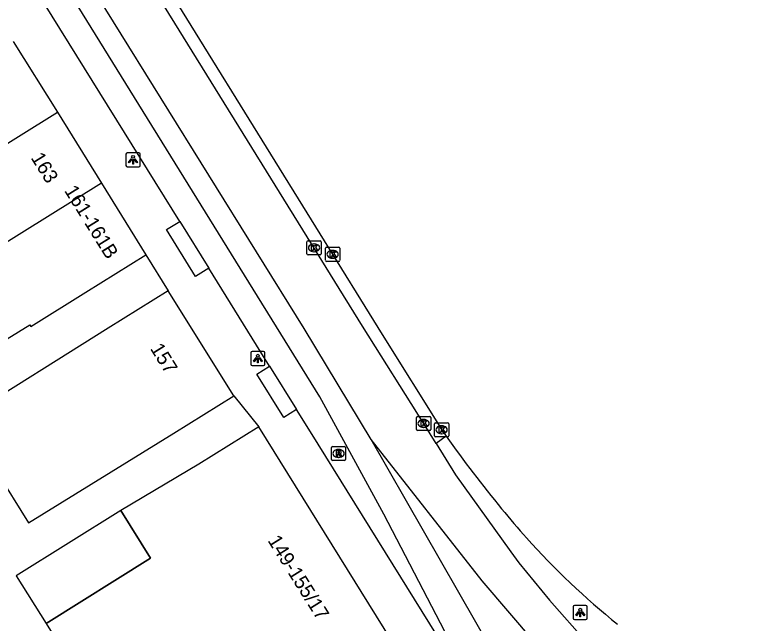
# Model space of a CAD drawing. Extents: x 159888 to 160757, y 384031 to 384746.
# Drawn here: x 160691.6 to 160744.8, y 384165.5 to 384208.5 of the extents above; entities that cross this region are included whole.
import ezdxf

# ---------------------------------------------------------------- set-up
doc = ezdxf.new("R2010")
doc.units = 0
for name, color, linetype in [('IMGEO_Berm_open', 7, 'Continuous'), ('IMGEO_Kolk', 7, 'Continuous'), ('IMGEO_Lichtpunt', 7, 'Continuous'), ('IMGEO_Pand', 7, 'Continuous'), ('IMGEO_Pand_nummerreeks', 7, 'Continuous'), ('IMGEO_Pand_overbouw', 7, 'Continuous'), ('IMGEO_Rijbaan_lokaal_gesloten', 7, 'Continuous'), ('IMGEO_Rioolput', 7, 'Continuous'), ('IMGEO_Voetpad_open', 7, 'Continuous')]:
    doc.layers.add(name, color=color, linetype=linetype)

msp = doc.modelspace()

# ---------------------------------------------------------------- linework, layer by layer
at = {"layer": 'IMGEO_Berm_open'}
msp.add_lwpolyline([(160722.103, 384178.75), (160721.392, 384178.231)], dxfattribs=at)
at = {"layer": 'IMGEO_Kolk'}
for p, q in [((160712.271, 384191.636), (160712.271, 384192.488)), ((160712.346, 384192.562), (160713.198, 384192.562)), ((160712.759, 384192.342), (160712.784, 384192.342)), ((160713.272, 384192.488), (160713.272, 384191.636)), ((160712.782, 384191.782), (160712.757, 384191.782)), ((160713.584, 384191.178), (160713.584, 384192.03)), ((160713.659, 384192.104), (160714.511, 384192.104)), ((160714.072, 384191.884), (160714.097, 384191.884)), ((160714.585, 384192.03), (160714.585, 384191.178)), ((160713.198, 384191.562), (160712.346, 384191.562)), ((160714.511, 384191.104), (160713.659, 384191.104)), ((160714.095, 384191.324), (160714.07, 384191.324)), ((160720.013, 384179.219), (160720.013, 384180.071)), ((160720.088, 384180.145), (160720.94, 384180.145)), ((160720.501, 384179.925), (160720.526, 384179.925)), ((160721.014, 384180.071), (160721.014, 384179.219)), ((160721.284, 384178.773), (160721.284, 384179.625)), ((160721.359, 384179.699), (160722.211, 384179.699)), ((160721.772, 384179.479), (160721.797, 384179.479)), ((160722.285, 384179.625), (160722.285, 384178.773)), ((160720.94, 384179.145), (160720.088, 384179.145)), ((160720.524, 384179.365), (160720.499, 384179.365)), ((160721.795, 384178.919), (160721.77, 384178.919)), ((160722.211, 384178.699), (160721.359, 384178.699))]:
    msp.add_line(p, q, dxfattribs=at)
for points in [[(160712.271, 384191.636), (160712.271, 384192.488)], [(160712.346, 384192.562), (160713.198, 384192.562)], [(160712.592, 384192.262), (160712.715, 384192.262), (160712.715, 384192.111), (160712.845, 384192.262), (160713.009, 384192.262), (160712.863, 384192.111), (160713.016, 384191.862), (160712.864, 384191.862), (160712.779, 384192.026), (160712.715, 384191.959), (160712.715, 384191.862), (160712.592, 384191.862), (160712.592, 384192.262)], [(160713.272, 384192.488), (160713.272, 384191.636)], [(160713.584, 384191.178), (160713.584, 384192.03)], [(160713.659, 384192.104), (160714.511, 384192.104)], [(160713.905, 384191.804), (160714.028, 384191.804), (160714.028, 384191.653), (160714.158, 384191.804), (160714.322, 384191.804), (160714.176, 384191.653), (160714.329, 384191.404), (160714.177, 384191.404), (160714.092, 384191.568), (160714.028, 384191.501), (160714.028, 384191.404), (160713.905, 384191.404), (160713.905, 384191.804)], [(160714.585, 384192.03), (160714.585, 384191.178)], [(160713.198, 384191.562), (160712.346, 384191.562)], [(160714.511, 384191.104), (160713.659, 384191.104)], [(160720.013, 384179.219), (160720.013, 384180.071)], [(160720.088, 384180.145), (160720.94, 384180.145)], [(160721.014, 384180.071), (160721.014, 384179.219)], [(160720.334, 384179.845), (160720.457, 384179.845), (160720.457, 384179.694), (160720.587, 384179.845), (160720.751, 384179.845), (160720.605, 384179.694), (160720.758, 384179.445), (160720.606, 384179.445), (160720.521, 384179.609), (160720.457, 384179.542), (160720.457, 384179.445), (160720.334, 384179.445), (160720.334, 384179.845)], [(160721.284, 384178.773), (160721.284, 384179.625)], [(160721.359, 384179.699), (160722.211, 384179.699)], [(160721.605, 384179.399), (160721.728, 384179.399), (160721.728, 384179.248), (160721.858, 384179.399), (160722.022, 384179.399), (160721.876, 384179.248), (160722.029, 384178.999), (160721.877, 384178.999), (160721.792, 384179.163), (160721.728, 384179.096), (160721.728, 384178.999), (160721.605, 384178.999), (160721.605, 384179.399)], [(160722.285, 384179.625), (160722.285, 384178.773)], [(160720.94, 384179.145), (160720.088, 384179.145)], [(160722.211, 384178.699), (160721.359, 384178.699)]]:
    msp.add_lwpolyline(points, dxfattribs=at)
for centre, start, end in [((160712.348, 384192.486), 91.552, 178.448), ((160712.348, 384192.486), 91.552, 178.448), ((160713.196, 384192.486), 1.552, 88.448), ((160713.196, 384192.486), 1.552, 88.448), ((160712.348, 384191.638), 181.552, 268.448), ((160712.348, 384191.638), 181.552, 268.448), ((160713.196, 384191.638), 271.552, 358.448), ((160713.196, 384191.638), 271.552, 358.448), ((160713.661, 384192.028), 91.552, 178.448), ((160713.661, 384192.028), 91.552, 178.448), ((160714.509, 384192.028), 1.552, 88.448), ((160714.509, 384192.028), 1.552, 88.448), ((160713.661, 384191.18), 181.552, 268.448), ((160713.661, 384191.18), 181.552, 268.448), ((160714.509, 384191.18), 271.552, 358.448), ((160714.509, 384191.18), 271.552, 358.448), ((160720.09, 384180.069), 91.552, 178.448), ((160720.09, 384180.069), 91.552, 178.448), ((160720.938, 384180.069), 1.552, 88.448), ((160720.938, 384180.069), 1.552, 88.448), ((160721.361, 384179.623), 91.552, 178.448), ((160721.361, 384179.623), 91.552, 178.448), ((160722.209, 384179.623), 1.552, 88.448), ((160722.209, 384179.623), 1.552, 88.448), ((160720.09, 384179.221), 181.552, 268.448), ((160720.09, 384179.221), 181.552, 268.448), ((160720.938, 384179.221), 271.552, 358.448), ((160720.938, 384179.221), 271.552, 358.448), ((160721.361, 384178.775), 181.552, 268.448), ((160721.361, 384178.775), 181.552, 268.448), ((160722.209, 384178.775), 271.552, 358.448), ((160722.209, 384178.775), 271.552, 358.448)]:
    msp.add_arc(centre, 0.0765, start, end, dxfattribs=at)
for centre, major_axis, ratio, start_param, end_param in [((160712.758, 384192.062), (-0.387, 0.002), 0.722429, 4.712389, 7.853982), ((160712.783, 384192.062), (-0.39, 0.002), 0.717154, 1.570796, 4.712389), ((160714.071, 384191.604), (-0.387, 0.002), 0.722429, 4.712389, 7.853982), ((160714.096, 384191.604), (-0.39, 0.002), 0.717154, 1.570796, 4.712389), ((160720.5, 384179.645), (-0.387, 0.002), 0.722429, 4.712389, 7.853982), ((160720.525, 384179.645), (-0.39, 0.002), 0.717154, 1.570796, 4.712389), ((160721.771, 384179.199), (-0.387, 0.002), 0.722429, 4.712389, 7.853982), ((160721.796, 384179.199), (-0.39, 0.002), 0.717154, 1.570796, 4.712389)]:
    msp.add_ellipse(centre, major_axis=major_axis, ratio=ratio, start_param=start_param, end_param=end_param, dxfattribs=at)
at = {"layer": 'IMGEO_Lichtpunt'}
for p, q in [((160699.483, 384198.691), (160699.483, 384197.884)), ((160699.483, 384198.691), (160699.483, 384197.884)), ((160700.385, 384198.786), (160699.577, 384198.786)), ((160700.385, 384198.786), (160699.577, 384198.786)), ((160700.479, 384197.884), (160700.479, 384198.691)), ((160700.479, 384197.884), (160700.479, 384198.691)), ((160699.577, 384197.79), (160700.385, 384197.79)), ((160699.577, 384197.79), (160700.385, 384197.79)), ((160709.206, 384184.733), (160708.398, 384184.733)), ((160709.206, 384184.733), (160708.398, 384184.733)), ((160708.304, 384184.638), (160708.304, 384183.831)), ((160708.304, 384184.638), (160708.304, 384183.831)), ((160709.3, 384183.831), (160709.3, 384184.638)), ((160709.3, 384183.831), (160709.3, 384184.638)), ((160708.398, 384183.737), (160709.206, 384183.737)), ((160708.398, 384183.737), (160709.206, 384183.737)), ((160731.082, 384166.679), (160731.082, 384165.872)), ((160731.082, 384166.679), (160731.082, 384165.872)), ((160731.984, 384166.774), (160731.176, 384166.774)), ((160731.984, 384166.774), (160731.176, 384166.774)), ((160732.078, 384165.872), (160732.078, 384166.679)), ((160732.078, 384165.872), (160732.078, 384166.679)), ((160731.176, 384165.778), (160731.984, 384165.778)), ((160731.176, 384165.778), (160731.984, 384165.778))]:
    msp.add_line(p, q, dxfattribs=at)
for points in [[(160699.857, 384198.355), (160699.896, 384198.327), (160699.708, 384198.065), (160699.67, 384198.092), (160699.857, 384198.355)], [(160699.959, 384198.307), (160700.006, 384198.307), (160700.006, 384197.985), (160699.959, 384197.985), (160699.959, 384198.307)], [(160700.069, 384198.327), (160700.107, 384198.354), (160700.294, 384198.092), (160700.255, 384198.064), (160700.069, 384198.327)], [(160708.678, 384184.302), (160708.717, 384184.274), (160708.529, 384184.012), (160708.491, 384184.039), (160708.678, 384184.302)], [(160708.78, 384184.254), (160708.827, 384184.254), (160708.827, 384183.932), (160708.78, 384183.932), (160708.78, 384184.254)], [(160708.89, 384184.274), (160708.928, 384184.301), (160709.115, 384184.039), (160709.076, 384184.011), (160708.89, 384184.274)], [(160731.456, 384166.343), (160731.495, 384166.315), (160731.307, 384166.053), (160731.269, 384166.08), (160731.456, 384166.343)], [(160731.558, 384166.295), (160731.605, 384166.295), (160731.605, 384165.973), (160731.558, 384165.973), (160731.558, 384166.295)], [(160731.668, 384166.315), (160731.706, 384166.342), (160731.893, 384166.08), (160731.854, 384166.052), (160731.668, 384166.315)]]:
    msp.add_lwpolyline(points, dxfattribs=at)
for centre in [(160699.982, 384198.489), (160708.803, 384184.436), (160731.581, 384166.477)]:
    msp.add_circle(centre, 0.0994, dxfattribs=at)
for centre, start, end in [((160699.577, 384198.691), 90, 180), ((160699.577, 384198.691), 90, 180), ((160700.385, 384198.691), 0, 90), ((160700.385, 384198.691), 0, 90), ((160699.577, 384197.884), 180, 270), ((160699.577, 384197.884), 180, 270), ((160700.385, 384197.884), 270, 0), ((160700.385, 384197.884), 270, 360), ((160708.398, 384184.638), 90, 180), ((160708.398, 384184.638), 90, 180), ((160709.206, 384184.638), 0, 90), ((160709.206, 384184.638), 0, 90), ((160708.398, 384183.831), 180, 270), ((160708.398, 384183.831), 180, 270), ((160709.206, 384183.831), 270, 0), ((160709.206, 384183.831), 270, 360), ((160731.176, 384166.679), 90, 180), ((160731.176, 384166.679), 90, 180), ((160731.984, 384166.679), 0, 90), ((160731.984, 384166.679), 0, 90), ((160731.176, 384165.872), 180, 270), ((160731.176, 384165.872), 180, 270), ((160731.984, 384165.872), 270, 0), ((160731.984, 384165.872), 270, 360)]:
    msp.add_arc(centre, 0.0946, start, end, dxfattribs=at)
at = {"layer": 'IMGEO_Pand'}
for points in [[(160691.525, 384206.661), (160694.635, 384201.648)], [(160686.554, 384196.619), (160694.635, 384201.648)], [(160694.635, 384201.648), (160697.746, 384196.634)], [(160697.746, 384196.634), (160686.466, 384189.61), (160682.168, 384187.071)], [(160697.746, 384196.634), (160700.889, 384191.569)], [(160682.168, 384187.071), (160685.264, 384182.037), (160692.696, 384186.608), (160692.769, 384186.489), (160696.64, 384188.933), (160700.889, 384191.569)], [(160702.471, 384189.025), (160698.231, 384186.375), (160688.005, 384179.977), (160692.588, 384172.612), (160702.872, 384178.949), (160707.112, 384181.599)], [(160707.112, 384181.599), (160702.471, 384189.025)], [(160708.874, 384179.395), (160704.627, 384176.756), (160699.109, 384173.495), (160701.225, 384170.114), (160693.84, 384165.492), (160698.329, 384158.321), (160695.073, 384156.283), (160693.698, 384158.48)], [(160719.777, 384161.847), (160708.874, 384179.395)]]:
    msp.add_lwpolyline(points, dxfattribs=at)
at = {"layer": 'IMGEO_Pand_overbouw'}
msp.add_lwpolyline([(160699.109, 384173.495), (160691.724, 384168.872), (160693.84, 384165.492), (160701.225, 384170.114)], close=True, dxfattribs=at)
at = {"layer": 'IMGEO_Rijbaan_lokaal_gesloten'}
for points in [[(160632.074, 384323.722), (160677.924, 384250), (160717.593, 384185.942), (160721.789, 384179.196), (160722.103, 384178.75)], [(160721.392, 384178.231), (160720.54, 384179.603), (160716.199, 384186.525), (160676.893, 384250), (160631.369, 384323.299)], [(160716.812, 384178.507), (160712.066, 384186.351), (160658.156, 384273.096), (160628.254, 384321.427)], [(160725.705, 384157.813), (160717.699, 384173.243), (160713.185, 384181.538), (160666.822, 384256.425), (160627.201, 384320.153), (160626.898, 384320.642)], [(160727.905, 384159.142), (160716.812, 384178.507)], [(160742.378, 384146.138), (160739.485, 384150.742), (160735.808, 384155.472), (160724.659, 384168.519), (160716.812, 384178.507)], [(160721.392, 384178.231), (160722.765, 384176.019), (160726.685, 384170.566), (160727.245, 384169.786), (160729.416, 384167.144), (160732.078, 384164.139), (160736.076, 384159.626), (160738.151, 384157.187), (160741.437, 384152.722), (160744.77, 384147.64)]]:
    msp.add_lwpolyline(points, dxfattribs=at)
for centre, radius, start, end in [((160794.117, 384229.677), 88.202, 215.26702, 219.46581), ((160768.923, 384208.391), 55.224, 219.0317, 221.8455), ((160768.503, 384208.016), 54.661, 221.8463, 231.1513)]:
    msp.add_arc(centre, radius, start, end, dxfattribs=at)
at = {"layer": 'IMGEO_Rioolput'}
for p, q in [((160714.001, 384177.098), (160714.001, 384177.95)), ((160714.076, 384178.024), (160714.928, 384178.024)), ((160714.489, 384177.804), (160714.514, 384177.804)), ((160715.002, 384177.95), (160715.002, 384177.098)), ((160714.928, 384177.024), (160714.076, 384177.024)), ((160714.512, 384177.244), (160714.487, 384177.244))]:
    msp.add_line(p, q, dxfattribs=at)
for points in [[(160714.001, 384177.098), (160714.001, 384177.95)], [(160714.076, 384178.024), (160714.928, 384178.024)], [(160715.002, 384177.95), (160715.002, 384177.098)], [(160714.59, 384177.722), (160714.338, 384177.724), (160714.338, 384177.324)], [(160714.338, 384177.324), (160714.462, 384177.324), (160714.462, 384177.486), (160714.473, 384177.486)], [(160714.516, 384177.643), (160714.462, 384177.643), (160714.462, 384177.562)], [(160714.462, 384177.562), (160714.514, 384177.562)], [(160714.52, 384177.457), (160714.591, 384177.324), (160714.731, 384177.324), (160714.666, 384177.45)], [(160714.928, 384177.024), (160714.076, 384177.024)]]:
    msp.add_lwpolyline(points, dxfattribs=at)
for centre, radius, start, end in [((160714.078, 384177.948), 0.0765, 91.552, 178.448), ((160714.078, 384177.948), 0.0765, 91.552, 178.448), ((160714.926, 384177.948), 0.0765, 1.552, 88.448), ((160714.926, 384177.948), 0.0765, 1.552, 88.448), ((160714.472, 384177.433), 0.0533, 26.0293, 88.6989), ((160714.498, 384177.751), 0.19, 274.7715, 282.9687), ((160714.522, 384177.547), 0.0964, 77.0061, 93.1865), ((160714.536, 384177.604), 0.0378, 276.6634, 79.6772), ((160714.589, 384177.612), 0.109, 350.3612, 89.416), ((160714.587, 384177.612), 0.112, 277.5842, 350.9817), ((160714.571, 384177.397), 0.108, 29.5134, 73.7905), ((160714.078, 384177.1), 0.0765, 181.552, 268.448), ((160714.078, 384177.1), 0.0765, 181.552, 268.448), ((160714.926, 384177.1), 0.0765, 271.552, 358.448), ((160714.926, 384177.1), 0.0765, 271.552, 358.448)]:
    msp.add_arc(centre, radius, start, end, dxfattribs=at)
for centre, major_axis, ratio, start_param, end_param in [((160714.488, 384177.524), (-0.387, 0.002), 0.722429, 4.712389, 7.853982), ((160714.513, 384177.524), (-0.39, 0.002), 0.717154, 1.570796, 4.712389)]:
    msp.add_ellipse(centre, major_axis=major_axis, ratio=ratio, start_param=start_param, end_param=end_param, dxfattribs=at)
at = {"layer": 'IMGEO_Voetpad_open'}
for points in [[(160703.28, 384193.928), (160690.34, 384214.758), (160687.066, 384220.06)], [(160705.339, 384190.616), (160704.405, 384190.036), (160702.347, 384193.349), (160703.28, 384193.928)], [(160703.28, 384193.928), (160705.339, 384190.616)], [(160700.889, 384191.569), (160702.471, 384189.025)], [(160709.635, 384183.701), (160705.339, 384190.616)], [(160711.54, 384180.634), (160710.632, 384180.07), (160708.727, 384183.137), (160709.635, 384183.701)], [(160709.635, 384183.701), (160711.54, 384180.634)], [(160707.112, 384181.599), (160708.874, 384179.395)], [(160725.705, 384157.813), (160712.528, 384179.044), (160711.54, 384180.634)]]:
    msp.add_lwpolyline(points, dxfattribs=at)

# ---------------------------------------------------------------- texts
at = {"layer": 'IMGEO_Pand_nummerreeks'}
for s, rotation, p in [('163', 301.9078, (160692.729, 384198.429)), ('161-161B', 301.9021, (160695.094, 384196.106)), ('157', 301.9078, (160701.161, 384184.94)), ('149-155/17', 302.0453, (160709.463, 384171.369))]:
    msp.add_text(s, height=1, rotation=rotation, dxfattribs=at).set_placement(p)

doc.saveas('drawing.dxf')
